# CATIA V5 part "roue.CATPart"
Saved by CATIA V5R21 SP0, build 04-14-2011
Part number: roue
Revision: A
Nomenclature: 3
Material "Aluminium": density 2710 kg/m3, Young's modulus 7e+10 Pa, Poisson ratio 0.346, thermal expansion 2.36e-05 1/K
Bounding box of the stored display mesh (mm): x -36.5 to 20, y -31 to 31, z -31 to 31
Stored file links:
  C:\Users\Olivier\Desktop\redaction CATIA (local)\CATIA\DONNEES\Exercice assemblage 1 (chassis et socle)\roue.CATPart
  C:\Program Files\Dassault Systemes\B21\win_b64\startup\materials\French\Catalog.CATMaterial
  C:\Program Files\Dassault Systemes\B21\win_b64\resources\graphic\figures\CATIA_EnvironmentMap_Satin_512x512.jpg
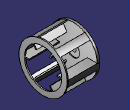
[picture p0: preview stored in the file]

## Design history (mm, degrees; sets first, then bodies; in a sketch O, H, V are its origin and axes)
Body1 (main body), material "Aluminium"
  Sketch1 on yz-plane, origin (0, 0, 0), H (0, 1, 0), V (0, 0, 1)
    arc A1 centre (0, 0) radius 31 from (21.7261, 22.1128) to (14.8459, 27.2139) ccw
    arc A2 centre (0, 0) radius 29.5 from (20.6749, 21.0428) to (15.3948, 25.1645) ccw
    line L1 (9.6319, 15.1829) -> (15.3948, 25.1645)
    line L2 (8.3328, 15.9329) -> (14.8459, 27.2139)
    construction line L3 (0, 0) -> (-1.299, 0.75)
    line L4 (20.6749, 21.0428) -> (21.7261, 22.1128)
    arc A3 centre (0, 0) radius 17.9804 from (9.6319, 15.1829) to (8.3328, 15.9329) ccw
    angle L1 H = 60
    distance L1 L2 = 1.5
    distance A1 A2 = 1.5
    radius A1 = 31
    perpendicularity: L3 L1, L3 L2
  Pad1: profile Sketch1, direction (1, 0, 0), length 20, mirrored extent
  Sketch2 on start face of Pad1, origin (-20, 0, 0), H (0, -1, 0), V (0, 0, 1)
    reference projected arc E1 centre (0, 0) radius 31 from (-14.8459, 27.2139) to (-21.7261, 22.1128) ccw from edge [start face of Pad1 | face of Pad1 from Sketch1.A1]
    circle A1 centre (0, 0) radius 31
    point P3 (-17.8616, 25.337)
    circle A2 centre (0, 0) radius 2.5
    circle A3 centre (0, 0) radius 8
    radius A2 = 2.5
    radius A3 = 8
    coincidence: A1 P3, P3 E1
  Sketch3 on end face of Pad1, origin (20, 0, 0), H (0, 1, 0), V (0, 0, 1)
    circle A1 centre (0, 0) radius 24
    circle A2 centre (0, 0) radius 31
    radius A1 = 24
    radius A2 = 31
  Pad2: profile Sketch3, direction (-1, 0, 0), length 1.5
  MultiPad1: profile Sketch2, domains (length 16.5; length 0; length 2 / length 1)
  Sketch4 on face of MultiPad1, origin (-36.5, 0, 0), H (0, -1, 0), V (0, 0, 1)
    circle A1 centre (0, 0) radius 4.5
  Pocket1: profile Sketch4, direction (1, 0, 0), length 12
  CircPattern1: of Pad1, instances 6, angular step 60, axis from end face of Pad2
